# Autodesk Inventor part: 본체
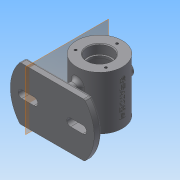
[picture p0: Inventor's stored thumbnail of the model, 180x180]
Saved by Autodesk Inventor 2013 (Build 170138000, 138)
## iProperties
Created: 2017-12
Part Number: 본체
Material: 일반
Document SubType Name: Modeling
Designer: Administrator
Density: 1 g/cm^3
Author: Administrator
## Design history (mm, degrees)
sketch "스케치1"
  geometry: C1 r 30 at (0, 0); 1 further point
  constraints: 1 centre point, 1 coincident
  dimensions: "d0" = 60 diameter of C1
extrude "돌출1" new body sketch "스케치1" stored distance "d1" = 70; taper "d2" = 0 deg
node "작업 평면1"
sketch "스케치3"
  geometry: L1 (42.426, 35)-(-42.426, 35); L2 (42.426, -35)-(-42.426, -35); L3 (24, 5)-(40, 5); L4 (40, -5)-(24, -5); L5 (-24, 5)-(-40, 5); L6 (-40, -5)-(-24, -5); L7 (5, 15)-(5, -15); L8 (-5, -15)-(-5, 15); A1 r 55 centre (0, 0) between (42.426, -35) and (42.426, 35); A2 r 55 centre (0, 0) between (-42.426, 35) and (-42.426, -35); A3 r 5 centre (40, 0) between (40, -5) and (40, 5); A4 r 5 centre (24, 0) between (24, 5) and (24, -5); A5 r 5 centre (-40, 0) between (-40, 5) and (-40, -5); A6 r 5 centre (-24, 0) between (-24, -5) and (-24, 5); A7 r 5 centre (0, 15) between (5, 15) and (-5, 15); A8 r 5 centre (0, -15) between (-5, -15) and (5, -15); 1 further point
  constraints: 16 end point, 16 point on circle, 12 tangent, 8 centre point, 6 parallel, 2 horizontal alignment, 1 coincident, 1 horizontal, 1 perpendicular, 1 vertical alignment
  dimensions: "d7" = 70 distance between parallel lines of L2 L1; "d8" = 35 distance from line of L1 point (0, 0); "d9" = 55 radius of A1; "d10" = 55 radius of A2; "d11" = 16 distance of L3.start L3.end; "d12" = 16 distance of L5.start L5.end; "d13" = 5 radius of A3; "d14" = 24 distance of point (0, 0) A4.centre; "d15" = 24 distance of point (0, 0) A6.centre; "d16" = 5 radius of A5; "d17" = 30 distance of L7.start L7.end; "d19" = 5 radius of A8; "d20" = 15 distance of A7.centre point (0, 0)
extrude "돌출2" join sketch "스케치3" distance "d21" = 10; taper "d22" = 0 deg
extrude "돌출3" join sketch "스케치3" stored distance "d23" = 10; taper "d24" = 0 deg
fillet "모깎기1" dims "d25" = 5
fillet "모깎기2" dims "d26" = 3
fillet "모깎기3" dims "d27" = 3
node "작업 평면2"
sketch "스케치4"
  geometry: C1 r 8 at (0, 0); 1 further point
  constraints: 1 centre point, 1 coincident
  dimensions: "d29" = 16 diameter of C1
extrude "돌출4" join sketch "스케치4" stored distance "d30" = 10; taper "d31" = 0 deg
sketch "스케치5"
  geometry: L1 (-30, 25)-(-30, 35) reference; L2 (-30, 35)-(30, 35) reference; L3 (30, 35)-(30, 8) reference; L4 (30, 8)-(37, 8) reference; L5 (37, 8)-(37, -8) reference; L6 (37, -8)-(30, -8) reference; L7 (30, -8)-(30, -35) reference; L8 (30, -35)-(-30, -35) reference; L9 (-30, -35)-(-30, -25) reference; L10 (-35, -20)-(-47, -20) reference; L11 (-52, -25)-(-52, -32) reference; L12 (-55, -35)-(-62, -35) reference; L13 (-62, -35)-(-62, 35) reference; L14 (-62, 35)-(-55, 35) reference; L15 (-52, 32)-(-52, 25) reference; L16 (-47, 20)-(-35, 20) reference; L17 (30, 35)-(-30, 35) reference; L18 (0, 35)-(0, -35); L19 (-30, -35)-(30, -35) reference; L20 (0, 35)-(16, 35); L21 (16, 35)-(16, 23.3); L22 (15.7, 23)-(14, 23); L23 (14, 23)-(14, 20); L24 (14, 20)-(22, 20); L25 (25, 17)-(25, -17); L26 (22, -20)-(14, -20); L27 (14, -20)-(14, -23); L28 (14, -23)-(15.7, -23); L29 (16, -23.3)-(16, -35); A1 r 5 centre (-47, -25) between (-47, -20) and (-52, -25) reference; A2 r 3 centre (-55, -32) between (-55, -35) and (-52, -32) reference; A3 r 3 centre (-55, 32) between (-52, 32) and (-55, 35) reference; A4 r 5 centre (-47, 25) between (-52, 25) and (-47, 20) reference; A5 r 3 centre (22, 17) between (25, 17) and (22, 20); A6 r 3 centre (22, -17) between (22, -20) and (25, -17); A7 r 0.3 centre (15.7, -23.3) between (16, -23.3) and (15.7, -23); A8 r 0.3 centre (15.7, 23.3) between (15.7, 23) and (16, 23.3); 4 further points
  constraints: 22 end point, 8 point on circle, 8 point on line, 8 tangent, 6 perpendicular, 4 centre point, 3 parallel, 2 equal radius, 2 midpoint, 1 vertical alignment, 2 other
  dimensions: "d32" = 16 distance of L18.start L20.end; "d33" = 12 distance of L20.end point (16, 23); "d34" = 3 distance of L22.end L23.end; "d35" = 40 distance of point (25, 20) point (25, -20); "d36" = 3 distance of L26.end L27.end; "d37" = 32 diameter of L29 L18; "d38" = 28 diameter of L23 L18; "d39" = 50 diameter of L25 L18; "d40" = 3 radius of A5; "d41" = 0.3 radius of A7
revolve "회전1" sketch "스케치5" stored, may be unused: angle "d42" = 90 deg
hole "구멍1" diameter "d45" = 8; stored, may be unused: countersink angle "d49" = 90 deg, drill point angle "d51" = 118 deg; dims "d43" = 10, "d44" = 10, "d46" = 6, "d47" = 4, "d48" = 2, "d50" = 30
sketch "스케치6"
  geometry: C1 r 16 at (0, 0) reference; 1 further point
  constraints: 1 vertical alignment
  dimensions: "d52" = 23 distance of C1.centre point (0, 23)
hole "구멍2" sketch "스케치6" at (0, 23) diameter "d53" = 3.242; stored, may be unused: countersink angle "d57" = 90 deg, drill point angle "d59" = 118 deg; dims "d54" = 8, "d55" = 4, "d56" = 2, "d58" = 10
node "작업 평면3"
sketch "스케치7"
  geometry: L1 (-30, -35)-(30, -35) reference; 2 further points
  constraints: 1 other
  dimensions: "d63" = 35 distance from line of L1 point (0, 0); "d64" = 30 horizontal distance of point (0, 0) L1.start
feature "엠보싱1" sketch "스케치7" dims "d7" = 70, "d8" = 35, "d9" = 55, "d10" = 55, "d11" = 16, "d12" = 16, "d13" = 5, "d14" = 24, "d15" = 24, "d16" = 5, "d17" = 30, "d19" = 5, "d20" = 15, "d65" = 0.5, "d66" = 0
chamfer "모따기1" distance "d67" = 1; stored, may be unused: second distance "d68" = 2, angle "d69" = 45 deg
fillet "모깎기4" dims "d70" = 3
node "솔리드1"
pattern_circular "원형 패턴1" dims angle "d61" = 360 deg
mirror "대칭1"
node "절단 모서리 투영2"
other parameters: "d3" = -62, "d28" = 37
